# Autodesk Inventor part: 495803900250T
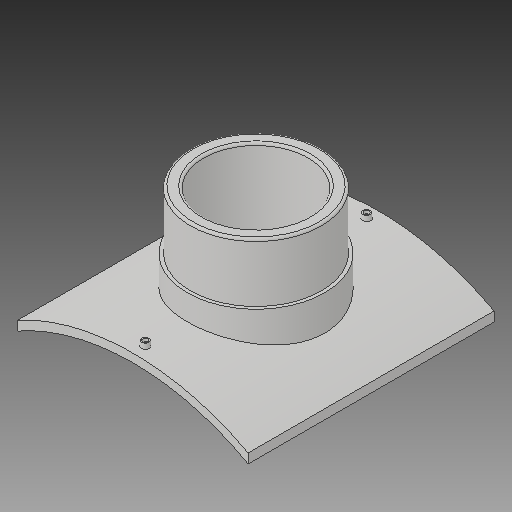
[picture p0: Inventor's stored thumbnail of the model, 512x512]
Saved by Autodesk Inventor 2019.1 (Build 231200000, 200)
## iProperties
Created: 2017-10
Part Number: 495803900250T
Material: Generic
Description: PLASSON BRANCH SADDLE 900x250
Document SubType Name: Modeling
Designer: KIM
Mass: 2754.05 g
Surface Area: 3037.44 cm^2
Volume: 2754.05 cm^3
Density: 1 g/cm^3
Appearance: Default
Author: KIM
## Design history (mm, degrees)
derived "495803.ipt"
feature "Solid1::495803.ipt"
tag "TaggingFeature1"
body "Solid1"
other parameters: "d1" = 16, "d4" = 0, "d12" = 475.6, "d13" = 14, "d14" = 211.5, "d16" = 5 deg, "d18" = 4, "d19" = 14, "d20" = 0, "d21" = 3, "d22" = 0, "d23" = 626, "d24" = 262.5, "d25" = 16, "d28" = 0, "d29" = 9.6, "d31" = 0, "d33" = 0, "d34" = 9, "d37" = 112, "d38" = 0, "d39" = 4.5, "x_" = 16, "D_" = 16
